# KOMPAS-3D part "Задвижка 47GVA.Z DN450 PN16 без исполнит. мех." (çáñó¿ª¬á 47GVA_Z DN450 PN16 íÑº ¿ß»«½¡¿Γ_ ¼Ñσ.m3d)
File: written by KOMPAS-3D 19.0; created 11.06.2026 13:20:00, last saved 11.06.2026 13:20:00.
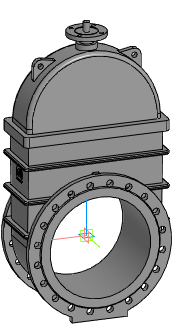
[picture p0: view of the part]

Document properties: Автор: Евгений; Полное имя файла: Z:\3.Личные\kachalov\001_3d для проектировщиков\2.2 Тип 47GVA, 47GVA.Z\_stp\_stp_Задвижка 47GVA.Z DN350-DN1200 без исп.мех\Задвижка 47GVA_Z DN450 PN16 без исполнит_ мех.m3d

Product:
- Part/product: Задвижка 47GVA.Z DN450 PN16 без исполнит. мех.

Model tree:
1. Операция без истории:1  (labels: Задвижка 47GVA.Z DN450 PN16 без исполнит. мех.)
